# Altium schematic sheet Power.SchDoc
size A4; PageSetup: Record=PageOptions嶤enterHorizontal=True嶤enterVertical=True嶱rintScale=0.98嶺Correction=1.00嶻Correction=1.00嶱rintKind=0嶣orderSize=5000000嶭eftOffset=0嶣ottomOffset=0嶰rientation=2嶱aperLength=1000嶱aperWidth=1000嶴cale=100嶱aperSource=7嶱rintQuality=-4嶮ediaType=1嶥itherType=10嶱aperKind=信纸嶱rintScaleMode=1
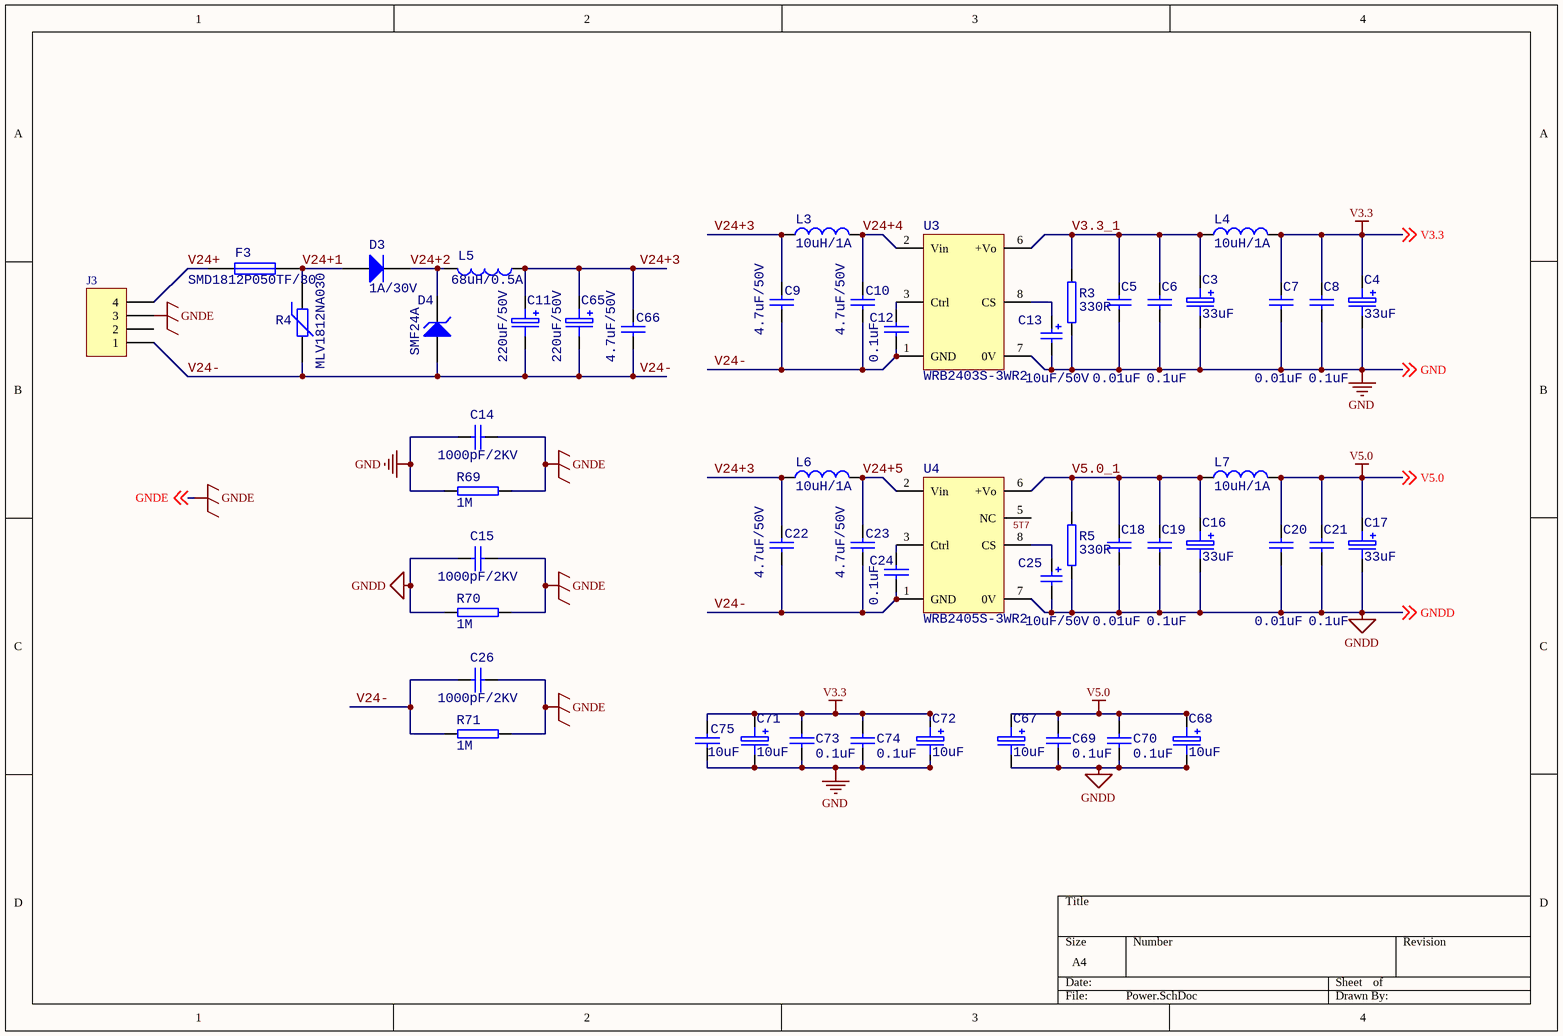
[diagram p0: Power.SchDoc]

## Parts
C3  33uF  [C3528(B)]
C4  33uF  [C3528(B)]
C5  0.01uF  [C1608(0603)]
C6  0.1uF  [C1608(0603)]
C7  0.01uF  [C1608(0603)]
C8  0.1uF  [C1608(0603)]
C9  4.7uF/50V  [C2012(0805)]
C10  4.7uF/50V  [C2012(0805)]
C11  220uF/50V  [CAPMP10X120]
C12  0.1uF  [C1608(0603)]
C13  10uF/50V  [C3216(1206)]
C14  1000pF/2KV  [C3216(1206)]
C15  1000pF/2KV  [C3216(1206)]
C16  33uF  [C3528(B)]
C17  33uF  [C3528(B)]
C18  0.01uF  [C1608(0603)]
C19  0.1uF  [C1608(0603)]
C20  0.01uF  [C1608(0603)]
C21  0.1uF  [C1608(0603)]
C22  4.7uF/50V  [C2012(0805)]
C23  4.7uF/50V  [C2012(0805)]
C24  0.1uF  [C1608(0603)]
C25  10uF/50V  [C3216(1206)]
C26  1000pF/2KV  [C3216(1206)]
C65  220uF/50V  [CAPMP10X120]
C66  4.7uF/50V  [C2012(0805)]
C67  10uF  [C3216(A)]
C68  10uF  [C3216(A)]
C69  0.1uF  [C1608(0603)]
C70  0.1uF  [C1608(0603)]
C71  10uF  [C3216(A)]
C72  10uF  [C3216(A)]
C73  0.1uF  [C1608(0603)]
C74  0.1uF  [C1608(0603)]
C75  10uF  [C2012(0805)]
D3  1A/30V  [SOD323]
D4  SMF24A  [SOD123]
F3  SMD1812P050TF/30  [R4532(1812)]
J3  Header 4  [MSTBO2.5/4-G1R]  (value not drawn)
L3  10uH/1A  [L4040]
L4  10uH/1A  [L4040]
L5  68uH/0.5A  [L4040]
L6  10uH/1A  [L4040]
L7  10uH/1A  [L4040]
R3  330R  [R3216(1206)]
R4  MLV1812NA030  [R4532(1812)]
R5  330R  [R3216(1206)]
R69  1M  [R3216(1206)]
R70  1M  [R3216(1206)]
R71  1M  [R3216(1206)]
U3  WRB2403S-3WR2  [SIP8]
U4  WRB2405S-3WR2  [SIP8]

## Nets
GND: C3.2 C4.2 C5.1 C6.1 C7.1 C8.1 C13.2 C14.1 C71.2 C72.2 C73.1 C74.1 C75.1 R3.2 R69.1 U3.7(0V) ; off-sheet GND
GNDD: C15.1 C16.2 C17.2 C18.1 C19.1 C20.1 C21.1 C25.2 C67.2 C68.2 C69.1 C70.1 R5.2 R70.1 U4.7(0V) ; off-sheet GNDD
GNDE: C14.2 C15.2 C26.2 J3.3 R69.2 R70.2 R71.2 ; off-sheet GNDE
V3.3: C4.1 C7.2 C8.2 C71.1 C72.1 C73.2 C74.2 C75.2 L4.2 ; off-sheet V3.3
V5.0: C17.1 C20.2 C21.2 C67.1 C68.1 C69.2 C70.2 L7.2 ; off-sheet V5.0
5T7: U4.5(NC)
V3.3_1: C3.1 C5.2 C6.2 L4.1 R3.1 U3.6(+Vo)
V5.0_1: C16.1 C18.2 C19.2 L7.1 R5.1 U4.6(+Vo)
V24+: F3.1 J3.4
V24+1: D3.1(A) F3.2 R4.1
V24+2: D3.2(K) D4.2(K) L5.2
V24+3: C9.2 C11.1 C22.2 C65.1 C66.2 L3.1 L5.1 L6.1
V24+4: C10.2 L3.2 U3.2(Vin)
V24+5: C23.2 L6.2 U4.2(Vin)
V24-: C9.1 C10.1 C11.2 C12.2 C22.1 C23.1 C24.2 C26.1 C65.2 C66.1 D4.1(A) J3.1 R4.2 R71.1 U3.1(GND) U4.1(GND)
NetC12_1: C12.1 U3.3(Ctrl)
NetC13_1: C13.1 U3.8(CS)
NetC24_1: C24.1 U4.3(Ctrl)
NetC25_1: C25.1 U4.8(CS)

Not connected (* = marked no-connect by the designer): J3 2; U3 5(NC)

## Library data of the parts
C3 C4 C11 C16 C17 C65 C67 C68 C71 C72 = CAPACITOR POL: CA45-?V?uF ABCD 16V10UF[A型3210]16V22UF(B型1210) 16V47UF(C型1812)
C5-C10 C12 C14 C15 C18-C24 C26 C66 C69 C70 C73-C75 = CAP: Capacitor
C13 C25 = Cap Pol2: Polarized Capacitor (Axial); Value: 100pF/100V
D3 = Diode: Default Diode
D4 = D Zener: Zener Diode
F3 = FUSE1: Fuse
J3 = Header 4: Header, 4-Pin
L3 L4 L6 L7 = Inductor: Code_IEC: 1005; Value: ABRACON
L5 = Inductor: Code_IEC: 1005; Value: SRN4018-680M/CD32-680K
R3 R5 R69-R71 = R
R4 = Res Varistor: Varistor (Voltage-Sensitive Resistor)
U3 U4 = WRA_S-1WR2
